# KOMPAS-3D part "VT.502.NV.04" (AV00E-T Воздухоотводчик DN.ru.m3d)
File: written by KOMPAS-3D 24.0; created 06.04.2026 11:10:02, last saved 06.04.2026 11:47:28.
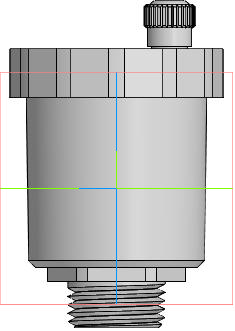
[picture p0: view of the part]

Document properties: Автор: R2D2; Полное имя файла: E:\Работа\Зайцев\Солянка\AV00E-T Воздухоотводчик DN.ru\Ду15 Ру10\исходные материалы\AV00E-T Воздухоотводчик DN.ru.m3d

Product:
- Body: Твердое тело1  | qty 1
    Масса: 0.487963
- Part/product: VT.502.NV.04
    Масса: 0.487963
    additional columns: Типовые

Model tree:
1. Твердое тело1  (labels: Твердое тело1)
2. Эскиз:1  (labels: Грань.Твердое тело1)
3. Элемент выдавливания:1
     Расстояние 1 = 0.5
4. Эскиз:2  (labels: Грань.Твердое тело1; Ребро.Твердое тело1)
5. Элемент выдавливания:2
     Расстояние 1 = 0.5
